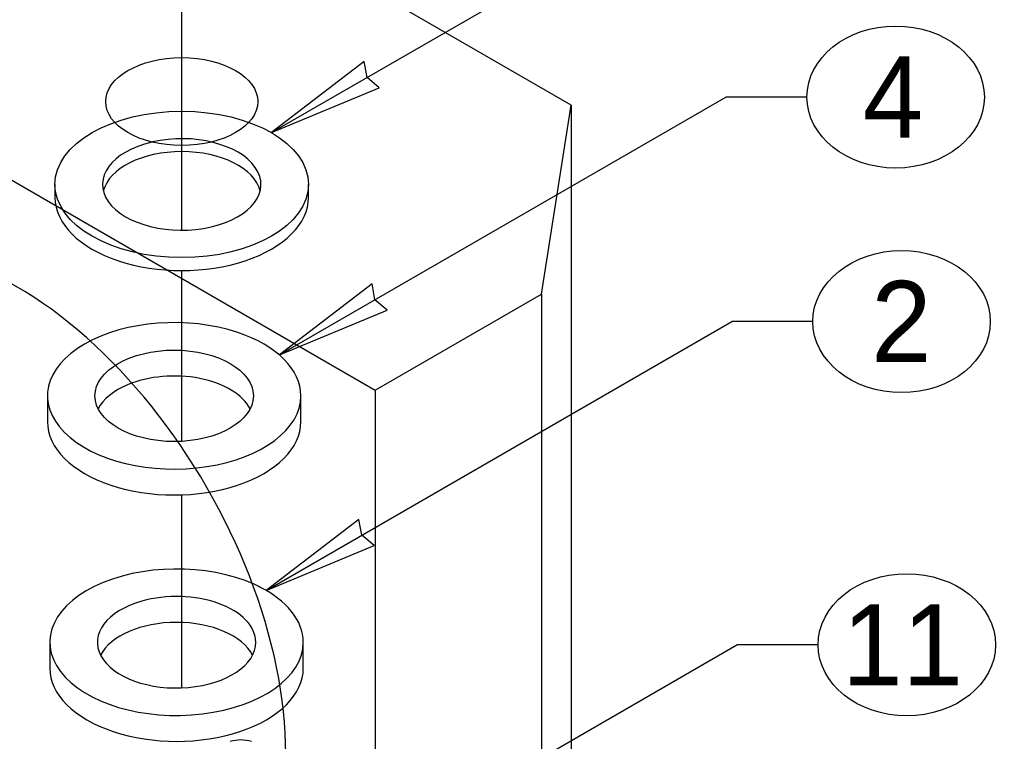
# Model space of a CAD drawing. Extents: x 99862 to 104211, y 98939 to 105076.
# Drawn here: x 102045.1 to 102237.6, y 101756.7 to 101899 of the extents above; entities that cross this region are included whole.
import ezdxf

# ---------------------------------------------------------------- set-up
doc = ezdxf.new("R2010")
doc.units = 0
for name, color, linetype in [('Level 11', 7, 'Continuous'), ('Level 15', 7, 'Continuous'), ('Level 2', 7, 'Continuous'), ('Level 20', 7, 'Continuous'), ('Level 26', 7, 'Continuous'), ('Level 4', 7, 'Continuous'), ('Level 5', 7, 'Continuous')]:
    doc.layers.add(name, color=color, linetype=linetype)

msp = doc.modelspace()

# ---------------------------------------------------------------- linework, layer by layer
at = {"layer": 'Level 11'}
for centre, major_axis, start_param, end_param in [((102076.12, 101776.27), (15.62, 0), 0, 2.024427), ((102076.12, 101776.27), (15.62, 0), 2.024427, 6.283185), ((102088.81, 101754.6), (-4.17, 0), 4.18879, 5.235988)]:
    msp.add_ellipse(centre, major_axis=major_axis, ratio=0.57735, start_param=start_param, end_param=end_param, dxfattribs=at)
at = {"layer": 'Level 15'}
for p, q in [((102094.82, 101876.72), (102184.45, 101928.47)), ((102077.14, 101857.49), (102077.14, 101900.8)), ((102096.39, 101832.89), (102184.45, 101883.73)), ((102200.45, 101883.73), (102184.45, 101883.73)), ((102077.14, 101815.86), (102077.14, 101849.53)), ((102093.8, 101786.48), (102185.61, 101839.48)), ((102201.61, 101839.48), (102185.61, 101839.48)), ((102077.14, 101767.27), (102077.14, 101805.33)), ((102094.82, 101722.77), (102186.63, 101775.77)), ((102202.63, 101775.77), (102186.63, 101775.77))]:
    msp.add_line(p, q, dxfattribs=at)
for points in [[(102094.82, 101876.72), (102116.08, 101885.55), (102113.68, 101887.61), (102113.1, 101890.72)], [(102096.39, 101832.89), (102117.66, 101841.72), (102115.25, 101843.78), (102114.67, 101846.89)], [(102093.8, 101786.48), (102115.06, 101795.31), (102112.66, 101797.37), (102112.08, 101800.48)]]:
    msp.add_lwpolyline(points, close=True, dxfattribs=at)
at = {"layer": 'Level 2'}
for p, q in [((102051.12, 101776.27), (102051.12, 101771.17)), ((102101.12, 101771.17), (102101.12, 101776.27))]:
    msp.add_line(p, q, dxfattribs=at)
for centre, major_axis, start_param, end_param in [((102076.12, 101776.27), (25, 0), 0.825055, 6.283185), ((102076.12, 101776.27), (25, 0), 6.283185, 7.149233), ((102076.12, 101771.17), (-15.62, 0), 3.428349, 5.996429), ((102076.12, 101771.17), (-25, 0), 0, 3.141593)]:
    msp.add_ellipse(centre, major_axis=major_axis, ratio=0.57735, start_param=start_param, end_param=end_param, dxfattribs=at)
at = {"layer": 'Level 20'}
for centre in [(102217.95, 101883.73), (102219.11, 101839.48), (102220.13, 101775.77)]:
    msp.add_ellipse(centre, major_axis=(-17.5, 0), ratio=0.8, dxfattribs=at)
at = {"layer": 'Level 26'}
for p, q in [((102153.96, 101882.14), (102091.44, 101918.24)), ((101973.9, 101907.58), (102115.32, 101825.93)), ((102148.09, 101844.85), (102153.96, 101882.14)), ((102153.96, 101882.14), (102153.96, 101732.86)), ((102115.32, 101825.93), (102148.09, 101844.85)), ((102148.09, 101844.85), (102148.09, 101690.86)), ((102115.32, 101825.93), (102115.32, 101664.37))]:
    msp.add_line(p, q, dxfattribs=at)
msp.add_ellipse((102077.14, 101882.84), major_axis=(15, 0), ratio=0.57735, dxfattribs=at)
msp.add_ellipse((102044.61, 101785.11), major_axis=(37.5, -64.95), ratio=0.57735, start_param=0, end_param=3.141593, dxfattribs=at)
at = {"layer": 'Level 4'}
for p, q in [((102050.65, 101824.84), (102050.65, 101819.73)), ((102100.65, 101819.73), (102100.65, 101824.84))]:
    msp.add_line(p, q, dxfattribs=at)
for centre, major_axis, start_param, end_param in [((102075.65, 101824.84), (25, 0), 1.046133, 6.283185), ((102075.65, 101824.84), (25, 0), 6.283185, 7.329318), ((102075.65, 101819.73), (-15.62, 0), 3.428349, 5.340377), ((102075.65, 101819.73), (-15.62, 0), 5.340377, 5.996429), ((102075.65, 101819.73), (-25, 0), 6.283185, 9.424778)]:
    msp.add_ellipse(centre, major_axis=major_axis, ratio=0.57735, start_param=start_param, end_param=end_param, dxfattribs=at)
msp.add_ellipse((102075.65, 101824.84), major_axis=(15.62, 0), ratio=0.57735, dxfattribs=at)
at = {"layer": 'Level 5'}
for p, q in [((102071.4, 101874.9), (102071.27, 101874.87)), ((102052.14, 101866.51), (102052.14, 101863.96)), ((102102.14, 101863.96), (102102.14, 101866.51))]:
    msp.add_line(p, q, dxfattribs=at)
msp.add_ellipse((102077.14, 101866.51), major_axis=(25, 0), ratio=0.57735, dxfattribs=at)
for centre, major_axis, start_param, end_param in [((102077.14, 101866.51), (15.62, 0), 1.95592, 8.230034), ((102077.14, 101863.96), (-15.62, 0), 3.28349, 6.141288), ((102077.14, 101863.96), (-25, 0), 6.283185, 9.424778)]:
    msp.add_ellipse(centre, major_axis=major_axis, ratio=0.57735, start_param=start_param, end_param=end_param, dxfattribs=at)

# ---------------------------------------------------------------- texts
at = {"layer": 'Level 20'}
for s, p in [('4', (102211.44, 101875.73)), ('2', (102213.12, 101831.49)), ('11', (102207.4, 101767.77))]:
    msp.add_text(s, height=16, dxfattribs=at).set_placement(p)

doc.saveas('drawing.dxf')
